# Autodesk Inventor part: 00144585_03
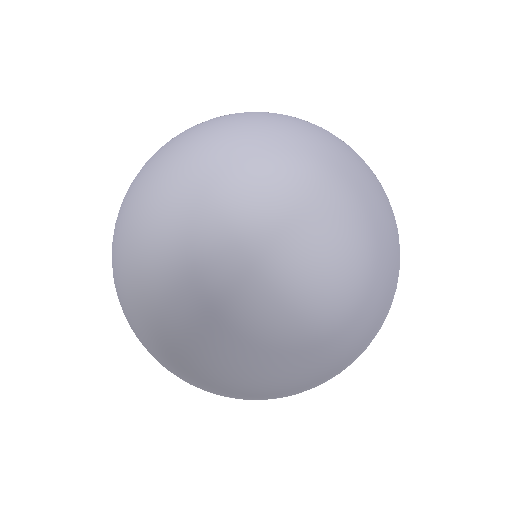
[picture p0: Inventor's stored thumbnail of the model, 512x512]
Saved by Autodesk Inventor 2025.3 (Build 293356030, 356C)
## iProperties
Created: 2021-02
Part Number: 00144585_03
Material: Generico
Document SubType Name: Modeling
Designer: R5800u
Density: 1 g/cm^3
Appearance: Default
Author: TraceParts
Sending System: SolidWorks 2021
Last Author: Albert
Last Saved: 2021-07-28
IsFastener: 1
TYPE: CATASM
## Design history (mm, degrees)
feature "Imported1"
node "Solido1"
